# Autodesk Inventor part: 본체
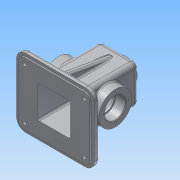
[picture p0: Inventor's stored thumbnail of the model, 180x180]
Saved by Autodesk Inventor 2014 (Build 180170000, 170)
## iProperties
Created: 2015-12
Part Number: 본체
Material: 알루미늄 6061
Document SubType Name: Modeling
Designer: Administrator
Density: 2.71 g/cm^3
Appearance: 알루미늄 - 평지
Mass: 803.08 g
Surface Area: 910.542 cm^2
Volume: 296.34 cm^3
Author: Administrator
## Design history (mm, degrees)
sketch "스케치1"
  geometry: L1 (32.5, -55)-(-32.5, -55); L2 (-32.5, -55)-(-32.5, 55); L3 (-32.5, 55)-(32.5, 55); L4 (32.5, 55)-(32.5, -55); L5 (32.5, -55)-(-32.5, 55); L6 (-32.5, -55)-(32.5, 55); 1 further point
  constraints: 12 end point, 2 midpoint, 2 parallel, 1 horizontal, 1 perpendicular
  dimensions: "d0" = 65 distance of L2.end L3.end; "d1" = 110 distance of L1.end L2.end
extrude "돌출1" new body sketch "스케치1" stored distance "d2" = 65; taper "d3" = 0 deg
sketch "스케치2"
  geometry: C1 r 20 at (32.5, 32.5); 1 further point
  constraints: 1 centre point, 1 coincident
  dimensions: "d4" = 40 diameter of C1
extrude "돌출2" join sketch "스케치2" distance "d5" = 10; taper "d6" = -5 deg
sketch "스케치3"
  geometry: C1 r 27.5 at (-32.5, 55); 1 further point
  constraints: 1 centre point, 1 coincident
  dimensions: "d7" = 55 diameter of C1
extrude "돌출3" join sketch "스케치3" distance "d8" = 15; taper "d9" = 0 deg
sketch "스케치4"
  geometry: C1 r 27.5 at (32.5, 55); 1 further point
  constraints: 1 centre point, 1 coincident
  dimensions: "d10" = 55 diameter of C1
extrude "돌출4" join sketch "스케치4" distance "d11" = 15; taper "d12" = 0 deg
sketch "스케치6"
  geometry: L1 (65, -65)-(65, 0) reference; L2 (0, 0)-(65, 0) reference; L3 (0, 0)-(0, -65) reference; L4 (65, -65)-(0, -65) reference; L5 (82.5, -85)-(-17.5, -85); L6 (-27.5, -75)-(-27.5, 10); L7 (-17.5, 20)-(82.5, 20); L8 (92.5, 10)-(92.5, -75); L9 (92.5, -85)-(-27.5, 20); L10 (-27.5, -85)-(92.5, 20); A1 r 10 centre (-17.5, 10) between (-17.5, 20) and (-27.5, 10); A2 r 10 centre (-17.5, -75) between (-27.5, -75) and (-17.5, -85); A3 r 10 centre (82.5, -75) between (82.5, -85) and (92.5, -75); A4 r 10 centre (82.5, 10) between (92.5, 10) and (82.5, 20); 1 further point
  constraints: 12 end point, 8 point on circle, 8 point on line, 8 tangent, 4 centre point, 3 equal radius, 2 midpoint, 2 parallel, 1 horizontal, 1 perpendicular
  dimensions: "d13" = 120 distance of L9.end L10.end; "d14" = 105 distance of L10.start L9.end; "d90" = 10 radius of A1
extrude "돌출5" join sketch "스케치6" distance "d15" = 2; taper "d16" = 0 deg
sketch "스케치7"
  geometry: L1 (-32.5, -25)-(97.5, -25); L2 (97.5, -25)-(97.5, 90); L3 (97.5, 90)-(-32.5, 90); L4 (-32.5, 90)-(-32.5, -25); L5 (-32.5, -25)-(97.5, 90); L6 (97.5, -25)-(-32.5, 90); 1 further point
  constraints: 12 end point, 2 midpoint, 2 parallel, 1 horizontal, 1 perpendicular
  dimensions: "d17" = 130 distance of L3.end L2.end; "d18" = 115 distance of L2.end L1.end
extrude "돌출6" join sketch "스케치7" distance "d19" = 8; taper "d20" = 0 deg
sketch "스케치8"
  geometry: L1 (-27.5, 75)-(-27.5, -10) reference; L2 (92.5, -10)-(92.5, 75) reference; L3 (82.5, 85)-(-17.5, 85) reference; L4 (-17.5, -20)-(82.5, -20) reference; L5 (-32.5, -25)-(97.5, -25) reference; L6 (97.5, 90)-(-32.5, 90) reference; L7 (-32.5, 90)-(-32.5, -25) reference; L8 (65, 0)-(65, 65) reference; L9 (32.5, 32.5)-(32.5, 46.814); C1 r 7.5 at (-17.5, 75); C2 r 7.5 at (-17.5, -10); C3 r 7.5 at (82.5, 75); C4 r 7.5 at (82.5, -10)
  constraints: 4 centre point, 2 end point, 2 symmetric about line, 1 parallel, 2 other
  dimensions: "d21" = 15 diameter of C1; "d91" = 15 distance from line of C1.centre L7; "d92" = 15 distance from line of C1.centre L6; "d93" = 15 diameter of C2; "d94" = 15 distance from line of C2.centre L7; "d95" = 15 distance from line of L5 C2.centre
extrude "돌출7" join sketch "스케치8" distance "d27" = 3; taper "d28" = 0 deg
sketch "스케치11"
  geometry: L1 (-55, 27.5)-(50, 27.5); L2 (50, 27.5)-(50, -27.5); L3 (50, -27.5)-(-55, -27.5); L4 (-55, -27.5)-(-55, 27.5); L5 (55, 32.5)-(55, -32.5) reference; L6 (-55, -42.5)-(-55, 42.5) reference; 2 further points
  constraints: 8 end point, 2 parallel, 1 horizontal, 1 perpendicular
  dimensions: "d32" = 55 distance of L1.end L2.end; "d33" = 5 distance between parallel lines of L2 L5; "d34" = 0 distance between parallel lines of L4 L6; "d35" = 5 distance from line of L5.start L1
extrude "돌출9" cut sketch "스케치11" stored distance "d36" = 55; taper "d37" = 0 deg
sketch "스케치12"
  geometry: C1 r 19.125 at (0, 0) reference; C2 r 10.5 at (0, 0)
  constraints: 1 centre point, 1 coincident
  dimensions: "d38" = 21 diameter of C2
extrude "돌출10" cut sketch "스케치12" distance "d39" = 30; taper "d40" = 0 deg
sketch "스케치14"
  geometry: L1 (0, 21)-(0, 0); L2 (0, 0)-(-21, 0); L3 (0, 0)-(0, -21); L4 (0, 0)-(21, 0); C1 r 27.5 at (0, 0) reference
  constraints: 8 end point, 3 perpendicular, 1 vertical
  dimensions: "d45" = 21 distance from line of L4.end L1; "d46" = 21 distance from line of L1.start L2; "d47" = 21 distance from line of L3.end L2; "d48" = 21 distance from line of L2.end L1
hole "구멍1" sketch "스케치14" at (0, 21), (-21, 0), (0, -21), (21, 0) diameter "d49" = 3.242; stored, may be unused: countersink angle "d53" = 90 deg, drill point angle "d55" = 118 deg; dims "d50" = 8, "d51" = 4, "d52" = 2, "d54" = 10
sketch "스케치15"
  geometry: L1 (0, 14.5)-(0, -14.5); L2 (-14.5, 0)-(14.5, 0); C1 r 10.5 at (0, 0) reference
  constraints: 4 end point, 1 perpendicular, 1 vertical
  dimensions: "d57" = 0 distance from line of C1.centre L2; "d58" = 0 distance from line of C1.centre L1; "d59" = 14.5 distance from line of L2.end L1; "d60" = 14.5 distance from line of L1.start L2; "d61" = 14.5 distance from line of L1.end L2; "d62" = 14.5 distance from line of L2.start L1
hole "구멍2" sketch "스케치15" at (0, 14.5), (-14.5, 0), (14.5, 0), (0, -14.5) diameter "d63" = 2.459; stored, may be unused: countersink angle "d67" = 90 deg, drill point angle "d69" = 118 deg; dims "d64" = 7, "d65" = 4, "d66" = 2, "d68" = 9
sketch "스케치16"
  geometry: L1 (-45, -57.5)-(-45, 57.5) reference; L2 (-45, 57.5)-(-45, 47.5); L3 (-45, 47.5)-(50.41, 30.677); L4 (50.41, 30.677)-(-45, 30.677); L5 (-45, 47.5)-(-45, 30.677); 1 further point
  constraints: 8 end point, 2 point on line, 1 collinear, 1 perpendicular
  dimensions: "d70" = 10 distance of L1.end L2.end; "d71" = 100 deg angle of L3 L2
extrude "돌출12" join sketch "스케치16" stored distance "d72" = 10; taper "d73" = 0 deg
sketch "스케치17"
  geometry: L1 (-32.5, -27.5)-(-47.5, -27.5) reference; L2 (-32.5, -45)-(-32.5, 55) reference; L3 (65, -45)-(-65, -45) reference; L4 (-42.5, -25.832)-(-42.5, -49.613); L5 (-27.5, 50)-(-27.5, -55) reference; L6 (-42.5, -25.832)-(-30.479, -25.832); L7 (-30.479, -25.832)-(-30.479, -49.613); L8 (-30.479, -49.613)-(-42.5, -49.613); 1 further point
  constraints: 8 end point, 3 perpendicular, 1 parallel
  dimensions: "d74" = 15 distance between parallel lines of L5 L4; "d75" = 2.02132 distance between parallel lines of L2 L7; "d76" = 1.66847 distance between parallel lines of L1 L6; "d77" = 22.11306 distance between parallel lines of L1 L8
extrude "돌출13" join sketch "스케치17" stored distance "d78" = 6; taper "d79" = 0 deg
sketch "스케치18"
  geometry: L1 (0, -100)-(0, 0) reference; L2 (13.375, 10)-(51.625, 10) reference; 1 further point
  constraints: 1 other
  dimensions: "d80" = 32.5 distance from line of point (32.5, -16) L1; "d81" = 26 distance from line of point (32.5, -16) L2
feature "엠보싱1" sketch "스케치18" dims "d82" = 0.5, "d83" = 0
fillet "모깎기1" dims "d84" = 8
fillet "모깎기2" dims "d85" = 8
chamfer "모따기1" distance "d86" = 1; stored, may be unused: second distance "d87" = 2, angle "d88" = 45 deg
fillet "모깎기3" dims "d89" = 15
sketch "스케치19"
  geometry: C1 r 7.5 at (0, 0) reference; C2 r 3 at (0, 0); C3 r 7.5 at (100, 0) reference; C4 r 7.5 at (100, -85) reference; C5 r 7.5 at (0, -85) reference; C6 r 3 at (0, -85); C7 r 3 at (100, -85); C8 r 3 at (100, 0); 1 further point
  constraints: 4 centre point, 4 coincident
  dimensions: "d96" = 6 diameter of C2; "d97" = 6 diameter of C6; "d98" = 6 diameter of C7; "d99" = 6 diameter of C8
extrude "돌출14" cut sketch "스케치19" stored distance "d100" = 6; taper "d101" = 0 deg
fillet "모깎기4" dims "d102" = 3
fillet "모깎기5" dims "d103" = 3
fillet "모깎기6" dims "d104" = 3
fillet "모깎기7" dims "d105" = 3
fillet "모깎기8" dims "d106" = 3
fillet "모깎기9" dims "d107" = 3
fillet "모깎기10" dims "d108" = 3
sketch "스케치20"
  geometry: C1 r 27.5 at (0, 0) reference; C2 r 17.5 at (0, 0)
  constraints: 1 centre point, 1 coincident
  dimensions: "d109" = 35 diameter of C2
extrude "돌출15" cut sketch "스케치20" distance "d110" = 17; taper "d111" = 0 deg
sketch "스케치22"
  geometry: C1 r 27.5 at (0, 0) reference; C2 r 17.5 at (0, 0)
  constraints: 1 centre point, 1 coincident
  dimensions: "d112" = 35 diameter of C2
extrude "돌출16" cut sketch "스케치22" distance "d113" = 17; taper "d114" = 0 deg
sketch "스케치23"
  geometry: C1 r 17.5 at (0, 0) reference; C2 r 15 at (0, 0)
  constraints: 1 centre point, 1 coincident
  dimensions: "d115" = 30 diameter of C2
extrude "돌출17" cut sketch "스케치23" stored distance "d116" = 17; taper "d117" = 0 deg
chamfer "모따기2" distance "d118" = 1; stored, may be unused: second distance "d119" = 2, angle "d120" = 45 deg
fillet "모깎기11" dims "d121" = 0.3
fillet "모깎기12" dims "d122" = 3
node "솔리드1"
mirror "대칭1"
mirror "대칭2"
mirror "대칭3"
node "투영된 루프1"
